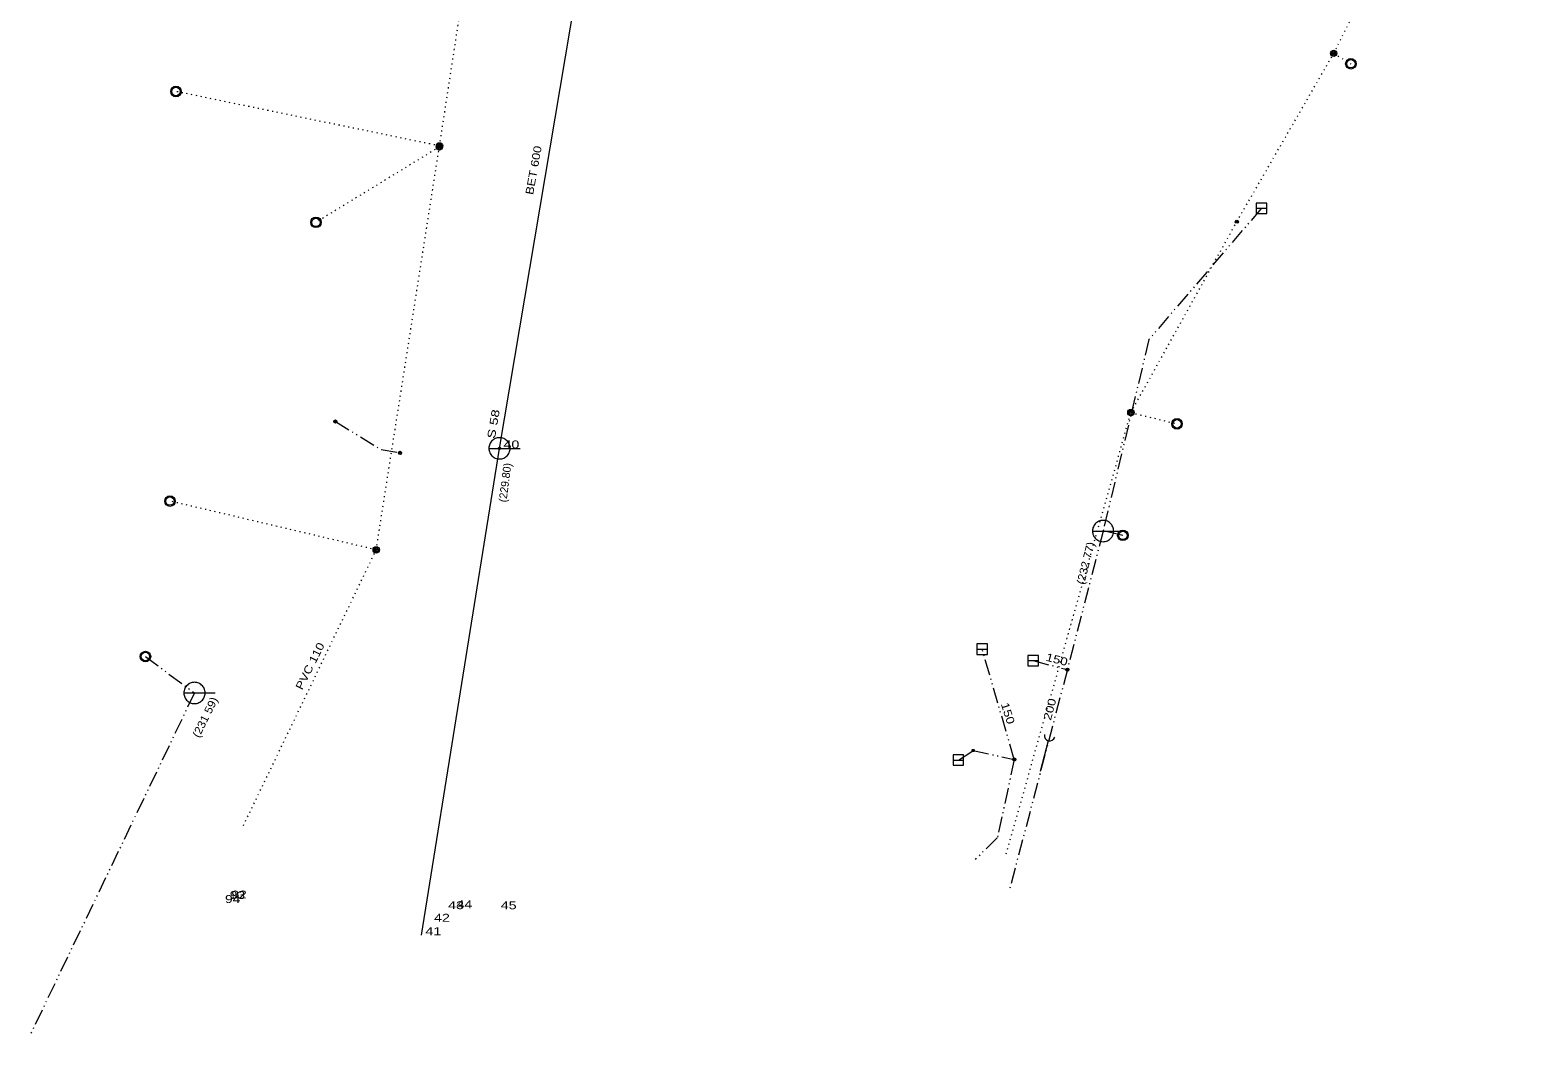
# Model space of a CAD drawing. Extents: x -648128 to -647962, y -1064951 to -1064761.
# Drawn here: x -648127.6 to -647984.8, y -1064950.5 to -1064855.2 of the extents above; entities that cross this region are included whole.
import ezdxf
from ezdxf.enums import TextEntityAlignment as Align

# ---------------------------------------------------------------- set-up
doc = ezdxf.new("R2010")
doc.units = 0
doc.header["$LTSCALE"] = 0.3
doc.header["$PDMODE"] = 32
doc.header["$PDSIZE"] = 0.15
doc.linetypes.add('DASH_DOUBLE_DOT', pattern=[9.2, 5, -1.2, 0.3, -1.2, 0.3, -1.2])
doc.linetypes.add('DOTTED', pattern=[1.5, 0.3, -1.2])
for name, color, linetype in [('1', 7, 'Continuous'), ('16', 7, 'Continuous'), ('18', 7, 'Continuous'), ('19', 7, 'Continuous'), ('2', 7, 'Continuous'), ('4', 7, 'Continuous')]:
    doc.layers.add(name, color=color, linetype=linetype)
for name, color, linetype, lineweight in [('10', 7, 'Continuous', 13), ('12', 7, 'Continuous', 13), ('30', 7, 'Continuous', 13), ('36', 7, 'DOTTED', 13), ('46', 7, 'Continuous', 13), ('5', 7, 'Continuous', 13), ('51', 7, 'DASH_DOUBLE_DOT', 13), ('59', 7, 'Continuous', 13)]:
    doc.layers.add(name, color=color, linetype=linetype, lineweight=lineweight)

msp = doc.modelspace()

# ---------------------------------------------------------------- linework, layer by layer
at = {"layer": '1'}
for p in [(-648083.14, -1064894.9), (-648029.32, -1064915.87), (-648038.26, -1064923.55), (-648034.36, -1064924.4)]:
    msp.add_point(p, dxfattribs=at)
at = {"layer": '10'}
for p, q in [((-648011.448, -1064872.141), (-648010.448, -1064872.141)), ((-648037.91, -1064913.94), (-648036.91, -1064913.94)), ((-648033.08, -1064915.03), (-648032.08, -1064915.03)), ((-648040.16, -1064924.45), (-648039.16, -1064924.45))]:
    msp.add_line(p, q, dxfattribs=at)
for points in [[(-648011.448, -1064872.641), (-648010.448, -1064872.641), (-648010.448, -1064871.641), (-648011.448, -1064871.641)], [(-648037.91, -1064914.44), (-648036.91, -1064914.44), (-648036.91, -1064913.44), (-648037.91, -1064913.44)], [(-648033.08, -1064915.53), (-648032.08, -1064915.53), (-648032.08, -1064914.53), (-648033.08, -1064914.53)], [(-648040.16, -1064924.95), (-648039.16, -1064924.95), (-648039.16, -1064923.95), (-648040.16, -1064923.95)]]:
    msp.add_lwpolyline(points, close=True, dxfattribs=at)
at = {"layer": '12'}
for p, q in [((-648084.148, -1064894.9), (-648081.171, -1064894.9)), ((-648026.958, -1064902.74), (-648023.981, -1064902.74)), ((-648113.048, -1064918.09), (-648110.071, -1064918.09))]:
    msp.add_line(p, q, dxfattribs=at)
for points in [[(-648083.14, -1064893.892), (-648083.245, -1064893.898), (-648083.349, -1064893.914), (-648083.451, -1064893.941), (-648083.549, -1064893.979), (-648083.643, -1064894.027), (-648083.731, -1064894.084), (-648083.814, -1064894.151), (-648083.889, -1064894.226), (-648083.955, -1064894.308), (-648084.012, -1064894.395), (-648084.059, -1064894.49), (-648084.097, -1064894.589), (-648084.125, -1064894.69), (-648084.141, -1064894.795), (-648084.148, -1064894.9), (-648084.141, -1064895.005), (-648084.125, -1064895.11), (-648084.097, -1064895.212), (-648084.059, -1064895.31), (-648084.012, -1064895.403), (-648083.955, -1064895.493), (-648083.889, -1064895.575), (-648083.814, -1064895.649), (-648083.731, -1064895.715), (-648083.643, -1064895.773), (-648083.549, -1064895.821), (-648083.451, -1064895.859), (-648083.349, -1064895.886), (-648083.245, -1064895.902), (-648083.14, -1064895.908), (-648083.034, -1064895.902), (-648082.929, -1064895.886), (-648082.828, -1064895.859), (-648082.73, -1064895.821), (-648082.635, -1064895.773), (-648082.547, -1064895.715), (-648082.465, -1064895.649), (-648082.39, -1064895.575), (-648082.324, -1064895.493), (-648082.267, -1064895.403), (-648082.218, -1064895.31), (-648082.18, -1064895.212), (-648082.154, -1064895.11), (-648082.138, -1064895.005), (-648082.132, -1064894.9), (-648082.138, -1064894.795), (-648082.154, -1064894.69), (-648082.18, -1064894.589), (-648082.218, -1064894.49), (-648082.267, -1064894.395), (-648082.324, -1064894.308), (-648082.39, -1064894.226), (-648082.465, -1064894.151), (-648082.547, -1064894.084), (-648082.635, -1064894.027), (-648082.73, -1064893.979), (-648082.828, -1064893.941), (-648082.929, -1064893.914), (-648083.034, -1064893.898)], [(-648025.95, -1064901.732), (-648026.055, -1064901.738), (-648026.159, -1064901.754), (-648026.261, -1064901.781), (-648026.359, -1064901.819), (-648026.453, -1064901.867), (-648026.541, -1064901.924), (-648026.624, -1064901.991), (-648026.699, -1064902.066), (-648026.765, -1064902.148), (-648026.822, -1064902.235), (-648026.869, -1064902.33), (-648026.907, -1064902.429), (-648026.935, -1064902.53), (-648026.951, -1064902.635), (-648026.958, -1064902.74), (-648026.951, -1064902.845), (-648026.935, -1064902.95), (-648026.907, -1064903.052), (-648026.869, -1064903.15), (-648026.822, -1064903.243), (-648026.765, -1064903.333), (-648026.699, -1064903.415), (-648026.624, -1064903.489), (-648026.541, -1064903.555), (-648026.453, -1064903.613), (-648026.359, -1064903.661), (-648026.261, -1064903.699), (-648026.159, -1064903.726), (-648026.055, -1064903.742), (-648025.95, -1064903.748), (-648025.844, -1064903.742), (-648025.739, -1064903.726), (-648025.638, -1064903.699), (-648025.54, -1064903.661), (-648025.445, -1064903.613), (-648025.357, -1064903.555), (-648025.275, -1064903.489), (-648025.2, -1064903.415), (-648025.134, -1064903.333), (-648025.077, -1064903.243), (-648025.028, -1064903.15), (-648024.99, -1064903.052), (-648024.964, -1064902.95), (-648024.948, -1064902.845), (-648024.942, -1064902.74), (-648024.948, -1064902.635), (-648024.964, -1064902.53), (-648024.99, -1064902.429), (-648025.028, -1064902.33), (-648025.077, -1064902.235), (-648025.134, -1064902.148), (-648025.2, -1064902.066), (-648025.275, -1064901.991), (-648025.357, -1064901.924), (-648025.445, -1064901.867), (-648025.54, -1064901.819), (-648025.638, -1064901.781), (-648025.739, -1064901.754), (-648025.844, -1064901.738)], [(-648112.04, -1064917.082), (-648112.145, -1064917.088), (-648112.249, -1064917.104), (-648112.351, -1064917.131), (-648112.449, -1064917.169), (-648112.543, -1064917.217), (-648112.631, -1064917.274), (-648112.714, -1064917.341), (-648112.789, -1064917.416), (-648112.855, -1064917.498), (-648112.912, -1064917.585), (-648112.959, -1064917.68), (-648112.997, -1064917.779), (-648113.025, -1064917.88), (-648113.041, -1064917.985), (-648113.048, -1064918.09), (-648113.041, -1064918.195), (-648113.025, -1064918.3), (-648112.997, -1064918.402), (-648112.959, -1064918.5), (-648112.912, -1064918.593), (-648112.855, -1064918.683), (-648112.789, -1064918.765), (-648112.714, -1064918.839), (-648112.631, -1064918.905), (-648112.543, -1064918.963), (-648112.449, -1064919.011), (-648112.351, -1064919.049), (-648112.249, -1064919.076), (-648112.145, -1064919.092), (-648112.04, -1064919.098), (-648111.934, -1064919.092), (-648111.829, -1064919.076), (-648111.728, -1064919.049), (-648111.63, -1064919.011), (-648111.535, -1064918.963), (-648111.447, -1064918.905), (-648111.365, -1064918.839), (-648111.29, -1064918.765), (-648111.224, -1064918.683), (-648111.167, -1064918.593), (-648111.118, -1064918.5), (-648111.08, -1064918.402), (-648111.054, -1064918.3), (-648111.038, -1064918.195), (-648111.032, -1064918.09), (-648111.038, -1064917.985), (-648111.054, -1064917.88), (-648111.08, -1064917.779), (-648111.118, -1064917.68), (-648111.167, -1064917.585), (-648111.224, -1064917.498), (-648111.29, -1064917.416), (-648111.365, -1064917.341), (-648111.447, -1064917.274), (-648111.535, -1064917.217), (-648111.63, -1064917.169), (-648111.728, -1064917.131), (-648111.829, -1064917.104), (-648111.934, -1064917.088)]]:
    msp.add_lwpolyline(points, close=True, dxfattribs=at)
at = {"layer": '30'}
for centre, radius in [((-648098.69, -1064892.35), 0.15), ((-648098.69, -1064892.35), 0.075), ((-648092.56, -1064895.33), 0.15), ((-648092.56, -1064895.33), 0.075), ((-648024.07, -1064903.15), 0.5), ((-648024.07, -1064903.15), 0.4), ((-648116.69, -1064914.64), 0.5), ((-648116.69, -1064914.64), 0.4), ((-648029.334, -1064915.879), 0.15), ((-648029.334, -1064915.879), 0.075), ((-648034.36, -1064924.4), 0.15), ((-648034.36, -1064924.4), 0.075)]:
    msp.add_circle(centre, radius, dxfattribs=at)
at = {"layer": '36'}
for p, q in [((-648004.096, -1064857.445), (-647984.756, -1064818.896)), ((-648088.822, -1064866.224), (-648085.203, -1064842.68)), ((-648013.279, -1064873.412), (-648004.096, -1064857.445)), ((-648094.82, -1064904.523), (-648088.837, -1064866.318)), ((-648088.837, -1064866.318), (-648088.822, -1064866.224)), ((-648023.315, -1064891.506), (-648013.279, -1064873.412)), ((-648035.121, -1064933.342), (-648023.315, -1064891.506)), ((-648107.402, -1064930.667), (-648094.82, -1064904.523))]:
    msp.add_line(p, q, dxfattribs=at)
at = {"layer": '46'}
for p, q in [((-648083.14, -1064894.9), (-648074.63, -1064844.44)), ((-648090.54, -1064941.06), (-648083.14, -1064894.9))]:
    msp.add_line(p, q, dxfattribs=at)
at = {"layer": '5'}
for centre, radius in [((-648004.096, -1064857.445), 0.3), ((-648004.096, -1064857.445), 0.2), ((-648004.096, -1064857.445), 0.1), ((-648002.466, -1064858.434), 0.5), ((-648002.466, -1064858.434), 0.4), ((-648113.796, -1064861.063), 0.5), ((-648113.796, -1064861.063), 0.4), ((-648088.837, -1064866.318), 0.3), ((-648088.822, -1064866.224), 0.3), ((-648088.837, -1064866.318), 0.2), ((-648088.822, -1064866.224), 0.2), ((-648088.837, -1064866.318), 0.1), ((-648088.822, -1064866.224), 0.1), ((-648100.531, -1064873.473), 0.5), ((-648100.531, -1064873.473), 0.4), ((-648013.279, -1064873.412), 0.15), ((-648013.279, -1064873.412), 0.075), ((-648023.315, -1064891.506), 0.3), ((-648023.315, -1064891.506), 0.2), ((-648023.315, -1064891.506), 0.1), ((-648018.946, -1064892.574), 0.5), ((-648018.946, -1064892.574), 0.4), ((-648114.362, -1064899.898), 0.5), ((-648114.362, -1064899.898), 0.4), ((-648094.82, -1064904.523), 0.3), ((-648094.82, -1064904.523), 0.2), ((-648094.82, -1064904.523), 0.1)]:
    msp.add_circle(centre, radius, dxfattribs=at)
at = {"layer": '51', "linetype": 'DOTTED'}
for p, q in [((-648004.096, -1064857.445), (-648002.466, -1064858.434)), ((-648088.822, -1064866.224), (-648113.796, -1064861.063)), ((-648088.837, -1064866.318), (-648100.531, -1064873.473)), ((-648023.315, -1064891.506), (-648018.946, -1064892.574)), ((-648094.82, -1064904.523), (-648114.362, -1064899.898))]:
    msp.add_line(p, q, dxfattribs=at)
at = {"layer": '51'}
for p, q in [((-648034.36, -1064924.4), (-648037.41, -1064913.94)), ((-648032.58, -1064915.03), (-648029.334, -1064915.879)), ((-648029.334, -1064915.879), (-648034.847, -1064936.827))]:
    msp.add_line(p, q, dxfattribs=at)
for points in [[(-648010.948, -1064872.141), (-648016.12, -1064878.18), (-648021.61, -1064884.59), (-648025.95, -1064902.74)], [(-648098.69, -1064892.35), (-648094.36, -1064895.02), (-648092.56, -1064895.33)], [(-648024.07, -1064903.15), (-648025.95, -1064902.74), (-648029.334, -1064915.879)], [(-648116.69, -1064914.64), (-648112.04, -1064918.09), (-648127.61, -1064950.51)], [(-648039.66, -1064924.45), (-648038.26, -1064923.55), (-648034.36, -1064924.4)], [(-648034.36, -1064924.4), (-648035.97, -1064931.83), (-648038.06, -1064933.87)]]:
    msp.add_lwpolyline(points, dxfattribs=at)
at = {"layer": '59'}
msp.add_line((-648031.144, -1064922.628), (-648031.902, -1064925.531), dxfattribs=at)
msp.add_arc((-648031.0177, -1064922.1446), 0.5, 165.36512, 345.36511, dxfattribs=at)

# ---------------------------------------------------------------- texts
at = {"layer": '16', "width": 1.2}
msp.add_text('PVC 110', height=0.75, rotation=63.42, dxfattribs=at).set_placement((-648100.7602, -1064915.7108), align=Align.CENTER)
at = {"layer": '18'}
for s, rotation, width, p in [('BET 600', 79.741, 1.2, (-648079.5427, -1064868.5963)), ('S 58', 80.427, 1.35, (-648083.3461, -1064892.6499))]:
    msp.add_text(s, height=0.75, rotation=rotation, dxfattribs=dict(at, width=width)).set_placement(p, align=Align.CENTER)
at = {"layer": '19', "width": 1.25}
for s, rotation, p in [('150', 345.447, (-648031.438, -1064915.018)), ('150', 288, (-648035.649, -1064919.14)), ('200', 75.454, (-648030.899, -1064920.745))]:
    msp.add_text(s, height=0.75, rotation=rotation, dxfattribs=at).set_placement(p)
at = {"layer": '2'}
for s, width, p in [(' 40', 1.35, (-648083.14, -1064894.9)), ('94', 1.3, (-648109.148, -1064938.005)), ('93', 1.3, (-648108.696, -1064937.629)), ('92', 1.3, (-648108.538, -1064937.578)), (' 43', 1.35, (-648088.38, -1064938.59)), (' 44', 1.35, (-648087.6, -1064938.51)), (' 45', 1.35, (-648083.4, -1064938.6)), (' 42', 1.35, (-648089.72, -1064939.78)), (' 41', 1.35, (-648090.54, -1064941.06))]:
    msp.add_text(s, height=0.75, dxfattribs=dict(at, width=width)).set_placement(p)
at = {"layer": '4'}
msp.add_text('(229.80)', height=0.75, rotation=82.558, dxfattribs=at).set_placement((-648082.482, -1064900.044))
at = {"layer": '4', "width": 1.1}
for s, rotation, p in [('(232 77)', 75.77, (-648027.748, -1064907.867)), ('(231 59)', 63.753, (-648111.602, -1064922.4))]:
    msp.add_text(s, height=0.75, rotation=rotation, dxfattribs=at).set_placement(p)

doc.saveas('drawing.dxf')
